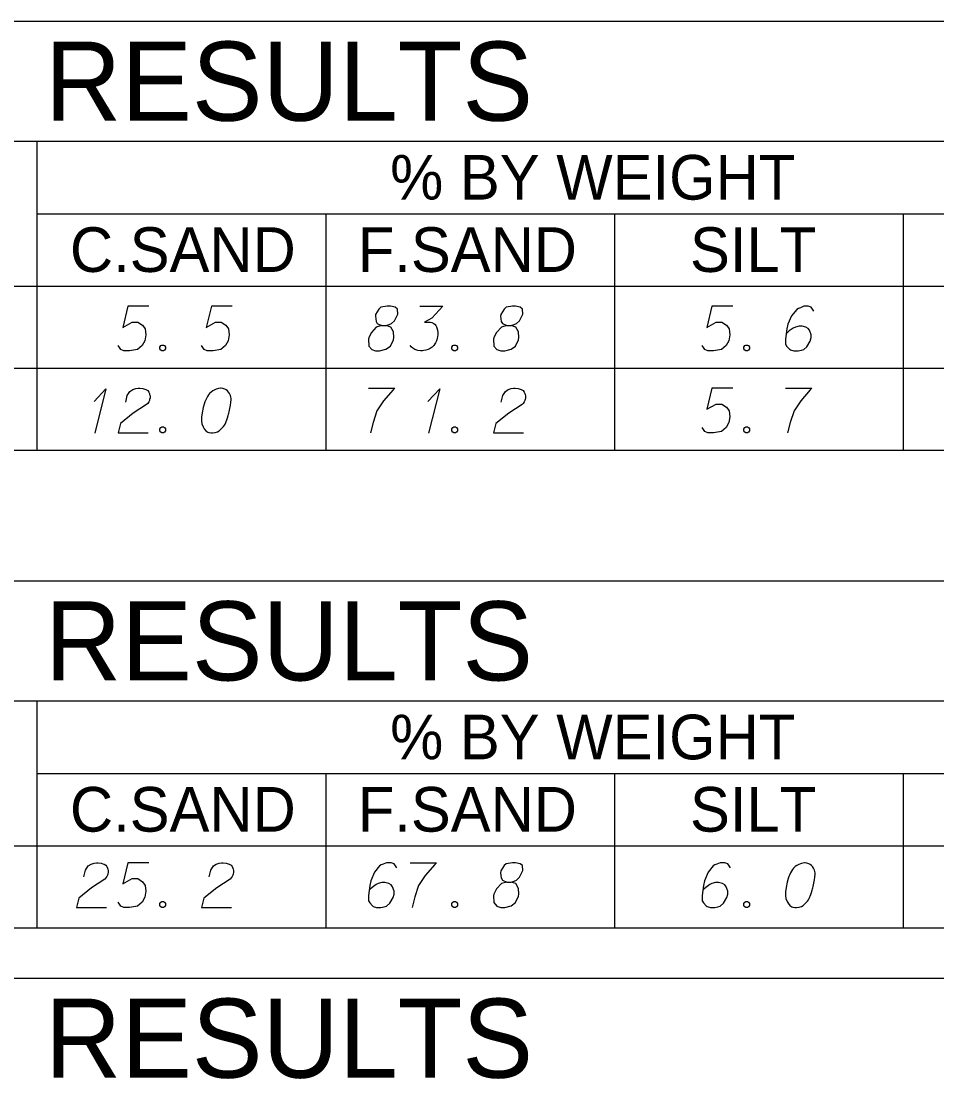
# Model space of a CAD drawing. Extents: x 2074207 to 2076812, y 516372 to 523312.
# Drawn here: x 2076524.4 to 2076622.7, y 516730.3 to 516843.9 of the extents above; entities that cross this region are included whole.
import ezdxf

# ---------------------------------------------------------------- set-up
doc = ezdxf.new("R2010")
doc.units = 0
for name, color, linetype in [('Prop DirtTable_ Soil Test Results - Outline (Major)', 7, 'Continuous'), ('Prop DirtTable_ Soil Test Results - Outline (Minor)', 7, 'Continuous'), ('Prop DirtTable_ Soil Test Results - Tx (Header - Large)', 7, 'Continuous'), ('Prop DirtTable_ Soil Test Results - Tx (Header - Small)', 7, 'Continuous'), ('Prop DirtTable_ Soil Test Results - Tx (Sample Data)', 7, 'Continuous')]:
    doc.layers.add(name, color=color, linetype=linetype)

msp = doc.modelspace()

# ---------------------------------------------------------------- linework, layer by layer
at = {"layer": 'Prop DirtTable_ Soil Test Results - Outline (Major)'}
for p, q in [((2076260.61, 516843.94), (2076811.9, 516843.94)), ((2076260.61, 516815.45), (2076811.9, 516815.45)), ((2076260.61, 516815.45), (2076811.9, 516815.45)), ((2076260.61, 516797.85), (2076811.9, 516797.85)), ((2076260.61, 516783.8), (2076811.9, 516783.8)), ((2076260.61, 516755.31), (2076811.9, 516755.31)), ((2076260.61, 516755.31), (2076811.9, 516755.31)), ((2076260.61, 516746.51), (2076811.9, 516746.51)), ((2076260.61, 516741.1), (2076811.9, 516741.1))]:
    msp.add_line(p, q, dxfattribs=at)
at = {"layer": 'Prop DirtTable_ Soil Test Results - Outline (Minor)'}
for p, q in [((2076260.61, 516831.05), (2076811.9, 516831.05)), ((2076526.07, 516831.05), (2076526.07, 516806.65)), ((2076526.07, 516823.25), (2076731.93, 516823.25)), ((2076557.09, 516823.25), (2076557.09, 516806.65)), ((2076588.11, 516823.25), (2076588.11, 516806.65)), ((2076619.13, 516806.65), (2076619.13, 516823.25)), ((2076260.61, 516806.65), (2076811.9, 516806.65)), ((2076260.61, 516806.65), (2076811.9, 516806.65)), ((2076526.07, 516806.65), (2076526.07, 516797.85)), ((2076557.09, 516806.65), (2076557.09, 516797.85)), ((2076588.11, 516806.65), (2076588.11, 516797.85)), ((2076619.13, 516797.85), (2076619.13, 516806.65)), ((2076260.61, 516797.85), (2076811.9, 516797.85)), ((2076260.61, 516770.91), (2076811.9, 516770.91)), ((2076526.07, 516770.91), (2076526.07, 516746.51)), ((2076526.07, 516763.11), (2076731.93, 516763.11)), ((2076557.09, 516763.11), (2076557.09, 516746.51)), ((2076588.11, 516763.11), (2076588.11, 516746.51)), ((2076619.13, 516746.51), (2076619.13, 516763.11)), ((2076260.61, 516746.51), (2076811.9, 516746.51))]:
    msp.add_line(p, q, dxfattribs=at)
at = {"layer": 'Prop DirtTable_ Soil Test Results - Tx (Sample Data)'}
for points in [[(2076538.08, 516813.3), (2076535.85, 516813.3), (2076535.29, 516811.03), (2076536.31, 516811.6), (2076536.91, 516811.6), (2076537.41, 516811.26), (2076537.69, 516810.88), (2076537.76, 516810.24), (2076537.65, 516809.6), (2076537.37, 516809.07), (2076536.88, 516808.65), (2076536.03, 516808.5), (2076535.4, 516808.5), (2076535.08, 516808.65), (2076534.8, 516809.07)], [(2076547.04, 516813.3), (2076544.81, 516813.3), (2076544.25, 516811.03), (2076545.27, 516811.6), (2076545.87, 516811.6), (2076546.37, 516811.26), (2076546.65, 516810.88), (2076546.72, 516810.24), (2076546.61, 516809.6), (2076546.33, 516809.07), (2076545.84, 516808.65), (2076544.99, 516808.5), (2076544.36, 516808.5), (2076544.04, 516808.65), (2076543.76, 516809.07)], [(2076563.09, 516811.22), (2076563.58, 516811.22), (2076563.72, 516811.26), (2076564.14, 516811.45), (2076564.46, 516811.75), (2076564.82, 516812.47), (2076564.78, 516813), (2076564.53, 516813.19), (2076564.04, 516813.3), (2076563.69, 516813.3), (2076563.02, 516813.19), (2076562.8, 516813), (2076562.45, 516812.43), (2076562.42, 516812.24), (2076562.49, 516811.67), (2076562.63, 516811.45), (2076563.09, 516811.22), (2076562.52, 516811.07), (2076561.99, 516810.5), (2076561.71, 516809.94), (2076561.68, 516809.75), (2076561.71, 516809.03), (2076562.03, 516808.65), (2076562.45, 516808.5), (2076562.87, 516808.5), (2076563.55, 516808.69), (2076564.04, 516809.03), (2076564.36, 516809.71), (2076564.39, 516809.94), (2076564.36, 516810.54), (2076564.07, 516811.07), (2076563.58, 516811.22)], [(2076567.18, 516813.3), (2076569.65, 516813.3), (2076568.48, 516812.01), (2076567.71, 516811.6), (2076568.34, 516811.6), (2076568.48, 516811.56), (2076568.55, 516811.52), (2076568.62, 516811.49), (2076568.7, 516811.45), (2076568.84, 516811.33), (2076568.91, 516811.22), (2076568.98, 516811.11), (2076569.01, 516810.99), (2076569.08, 516810.73), (2076569.12, 516810.5), (2076569.12, 516810.39), (2076569.12, 516810.24), (2076569.08, 516810.01), (2076569.05, 516809.86), (2076569.01, 516809.71), (2076568.98, 516809.6), (2076568.94, 516809.52), (2076568.91, 516809.44), (2076568.87, 516809.37), (2076568.8, 516809.26), (2076568.7, 516809.1), (2076568.59, 516808.99), (2076568.52, 516808.92), (2076568.41, 516808.84), (2076568.31, 516808.76), (2076568.17, 516808.69), (2076568.1, 516808.65), (2076567.85, 516808.58), (2076567.64, 516808.54), (2076567.5, 516808.5), (2076567.25, 516808.5), (2076566.97, 516808.54), (2076566.86, 516808.58), (2076566.76, 516808.61), (2076566.65, 516808.65), (2076566.54, 516808.73), (2076566.44, 516808.8), (2076566.26, 516808.95), (2076566.16, 516809.1)], [(2076576.53, 516811.22), (2076577.02, 516811.22), (2076577.16, 516811.26), (2076577.58, 516811.45), (2076577.9, 516811.75), (2076578.26, 516812.47), (2076578.22, 516813), (2076577.97, 516813.19), (2076577.48, 516813.3), (2076577.13, 516813.3), (2076576.46, 516813.19), (2076576.24, 516813), (2076575.89, 516812.43), (2076575.86, 516812.24), (2076575.93, 516811.67), (2076576.07, 516811.45), (2076576.53, 516811.22), (2076575.96, 516811.07), (2076575.43, 516810.5), (2076575.15, 516809.94), (2076575.12, 516809.75), (2076575.15, 516809.03), (2076575.47, 516808.65), (2076575.89, 516808.5), (2076576.31, 516808.5), (2076576.99, 516808.69), (2076577.48, 516809.03), (2076577.8, 516809.71), (2076577.83, 516809.94), (2076577.8, 516810.54), (2076577.51, 516811.07), (2076577.02, 516811.22)], [(2076600.8, 516813.3), (2076598.57, 516813.3), (2076598.01, 516811.03), (2076599.03, 516811.6), (2076599.63, 516811.6), (2076600.13, 516811.26), (2076600.41, 516810.88), (2076600.48, 516810.24), (2076600.37, 516809.6), (2076600.09, 516809.07), (2076599.6, 516808.65), (2076598.75, 516808.5), (2076598.12, 516808.5), (2076597.8, 516808.65), (2076597.52, 516809.07)], [(2076609.51, 516812.77), (2076609.23, 516813.19), (2076608.91, 516813.3), (2076608.42, 516813.3), (2076608.06, 516813.15), (2076607.85, 516813.07), (2076607.67, 516812.96), (2076607.11, 516812.28), (2076606.72, 516811.37), (2076606.62, 516810.88), (2076606.48, 516809.78), (2076606.48, 516809.22), (2076606.62, 516808.99), (2076606.9, 516808.69), (2076607, 516808.61), (2076607.36, 516808.5), (2076607.82, 516808.5), (2076608.17, 516808.58), (2076608.42, 516808.65), (2076608.77, 516808.95), (2076609.12, 516809.56), (2076609.23, 516809.94), (2076609.23, 516810.24), (2076609.05, 516810.73), (2076608.91, 516810.92), (2076608.66, 516811.07), (2076608.24, 516811.18), (2076607.92, 516811.18), (2076607.53, 516811.07), (2076607.29, 516810.96), (2076606.86, 516810.65), (2076606.65, 516810.46), (2076606.55, 516810.35)], [(2076539.49, 516809.14), (2076539.66, 516809.14), (2076539.77, 516809.07), (2076539.88, 516808.92), (2076539.88, 516808.73), (2076539.77, 516808.58), (2076539.66, 516808.5), (2076539.49, 516808.5), (2076539.38, 516808.58), (2076539.28, 516808.73), (2076539.28, 516808.92), (2076539.38, 516809.07), (2076539.49, 516809.14)], [(2076570.85, 516809.14), (2076571.02, 516809.14), (2076571.13, 516809.07), (2076571.24, 516808.92), (2076571.24, 516808.73), (2076571.13, 516808.58), (2076571.02, 516808.5), (2076570.85, 516808.5), (2076570.74, 516808.58), (2076570.64, 516808.73), (2076570.64, 516808.92), (2076570.74, 516809.07), (2076570.85, 516809.14)], [(2076602.21, 516809.14), (2076602.38, 516809.14), (2076602.49, 516809.07), (2076602.6, 516808.92), (2076602.6, 516808.73), (2076602.49, 516808.58), (2076602.38, 516808.5), (2076602.21, 516808.5), (2076602.1, 516808.58), (2076602, 516808.73), (2076602, 516808.92), (2076602.1, 516809.07), (2076602.21, 516809.14)], [(2076532.22, 516803.06), (2076533.49, 516804.42), (2076532.29, 516799.66)], [(2076535.61, 516802.99), (2076535.78, 516803.71), (2076536.07, 516804.16), (2076536.38, 516804.35), (2076536.7, 516804.46), (2076536.95, 516804.5), (2076537.12, 516804.5), (2076537.44, 516804.46), (2076537.65, 516804.39), (2076537.76, 516804.35), (2076537.97, 516804.24), (2076538.08, 516804.08), (2076538.15, 516803.93), (2076538.18, 516803.82), (2076538.22, 516803.67), (2076538.22, 516803.48), (2076538.18, 516803.29), (2076538.15, 516803.18), (2076538.08, 516803.03), (2076537.97, 516802.87), (2076537.86, 516802.76), (2076536.42, 516801.82), (2076535.04, 516800.72), (2076534.8, 516799.7), (2076538.01, 516799.7)], [(2076545.87, 516804.5), (2076545.8, 516804.5), (2076545.59, 516804.46), (2076545.45, 516804.42), (2076545.34, 516804.39), (2076545.17, 516804.31), (2076544.95, 516804.2), (2076544.78, 516804.08), (2076544.6, 516803.93), (2076544.5, 516803.78), (2076544.39, 516803.59), (2076544.28, 516803.4), (2076544.18, 516803.18), (2076544.11, 516803.03), (2076544.04, 516802.8), (2076543.93, 516802.42), (2076543.83, 516801.85), (2076543.76, 516801.4), (2076543.76, 516800.98), (2076543.79, 516800.68), (2076543.93, 516800.34), (2076544.04, 516800.15), (2076544.21, 516799.93), (2076544.43, 516799.78), (2076544.53, 516799.74), (2076544.74, 516799.7), (2076544.92, 516799.7), (2076545.2, 516799.74), (2076545.45, 516799.81), (2076545.63, 516799.93), (2076545.87, 516800.12), (2076545.98, 516800.23), (2076546.12, 516800.38), (2076546.22, 516800.53), (2076546.3, 516800.64), (2076546.37, 516800.83), (2076546.4, 516800.91), (2076546.47, 516801.1), (2076546.54, 516801.32), (2076546.61, 516801.55), (2076546.65, 516801.7), (2076546.68, 516801.82), (2076546.72, 516801.97), (2076546.79, 516802.31), (2076546.82, 516802.5), (2076546.86, 516802.69), (2076546.9, 516802.95), (2076546.93, 516803.29), (2076546.93, 516803.4), (2076546.9, 516803.55), (2076546.86, 516803.71), (2076546.75, 516803.93), (2076546.65, 516804.08), (2076546.54, 516804.2), (2076546.4, 516804.31), (2076546.26, 516804.39), (2076546.15, 516804.42), (2076546.05, 516804.46), (2076545.87, 516804.5)], [(2076561.68, 516804.5), (2076564.5, 516804.5), (2076564.32, 516804.31), (2076563.3, 516803.14), (2076562.59, 516802.08), (2076562.17, 516800.83), (2076561.89, 516799.7)], [(2076568.06, 516803.06), (2076569.33, 516804.42), (2076568.13, 516799.66)], [(2076575.93, 516802.99), (2076576.1, 516803.71), (2076576.39, 516804.16), (2076576.7, 516804.35), (2076577.02, 516804.46), (2076577.27, 516804.5), (2076577.44, 516804.5), (2076577.76, 516804.46), (2076577.97, 516804.39), (2076578.08, 516804.35), (2076578.29, 516804.24), (2076578.4, 516804.08), (2076578.47, 516803.93), (2076578.5, 516803.82), (2076578.54, 516803.67), (2076578.54, 516803.48), (2076578.5, 516803.29), (2076578.47, 516803.18), (2076578.4, 516803.03), (2076578.29, 516802.87), (2076578.18, 516802.76), (2076576.74, 516801.82), (2076575.36, 516800.72), (2076575.12, 516799.7), (2076578.33, 516799.7)], [(2076600.8, 516804.5), (2076598.57, 516804.5), (2076598.01, 516802.23), (2076599.03, 516802.8), (2076599.63, 516802.8), (2076600.13, 516802.46), (2076600.41, 516802.08), (2076600.48, 516801.44), (2076600.37, 516800.8), (2076600.09, 516800.27), (2076599.6, 516799.85), (2076598.75, 516799.7), (2076598.12, 516799.7), (2076597.8, 516799.85), (2076597.52, 516800.27)], [(2076606.48, 516804.5), (2076609.3, 516804.5), (2076609.12, 516804.31), (2076608.1, 516803.14), (2076607.39, 516802.08), (2076606.97, 516800.83), (2076606.69, 516799.7)], [(2076539.49, 516800.34), (2076539.66, 516800.34), (2076539.77, 516800.27), (2076539.88, 516800.12), (2076539.88, 516799.93), (2076539.77, 516799.78), (2076539.66, 516799.7), (2076539.49, 516799.7), (2076539.38, 516799.78), (2076539.28, 516799.93), (2076539.28, 516800.12), (2076539.38, 516800.27), (2076539.49, 516800.34)], [(2076570.85, 516800.34), (2076571.02, 516800.34), (2076571.13, 516800.27), (2076571.24, 516800.12), (2076571.24, 516799.93), (2076571.13, 516799.78), (2076571.02, 516799.7), (2076570.85, 516799.7), (2076570.74, 516799.78), (2076570.64, 516799.93), (2076570.64, 516800.12), (2076570.74, 516800.27), (2076570.85, 516800.34)], [(2076602.21, 516800.34), (2076602.38, 516800.34), (2076602.49, 516800.27), (2076602.6, 516800.12), (2076602.6, 516799.93), (2076602.49, 516799.78), (2076602.38, 516799.7), (2076602.21, 516799.7), (2076602.1, 516799.78), (2076602, 516799.93), (2076602, 516800.12), (2076602.1, 516800.27), (2076602.21, 516800.34)], [(2076531.13, 516751.99), (2076531.3, 516752.71), (2076531.59, 516753.16), (2076531.9, 516753.35), (2076532.22, 516753.46), (2076532.47, 516753.5), (2076532.64, 516753.5), (2076532.96, 516753.46), (2076533.17, 516753.39), (2076533.28, 516753.35), (2076533.49, 516753.24), (2076533.6, 516753.09), (2076533.67, 516752.93), (2076533.7, 516752.82), (2076533.74, 516752.67), (2076533.74, 516752.48), (2076533.7, 516752.29), (2076533.67, 516752.18), (2076533.6, 516752.03), (2076533.49, 516751.88), (2076533.38, 516751.76), (2076531.94, 516750.82), (2076530.56, 516749.72), (2076530.32, 516748.7), (2076533.53, 516748.7)], [(2076538.08, 516753.5), (2076535.85, 516753.5), (2076535.29, 516751.23), (2076536.31, 516751.8), (2076536.91, 516751.8), (2076537.41, 516751.46), (2076537.69, 516751.08), (2076537.76, 516750.44), (2076537.65, 516749.8), (2076537.37, 516749.27), (2076536.88, 516748.85), (2076536.03, 516748.7), (2076535.4, 516748.7), (2076535.08, 516748.85), (2076534.8, 516749.27)], [(2076544.57, 516751.99), (2076544.74, 516752.71), (2076545.03, 516753.16), (2076545.34, 516753.35), (2076545.66, 516753.46), (2076545.91, 516753.5), (2076546.08, 516753.5), (2076546.4, 516753.46), (2076546.61, 516753.39), (2076546.72, 516753.35), (2076546.93, 516753.24), (2076547.04, 516753.09), (2076547.11, 516752.93), (2076547.14, 516752.82), (2076547.18, 516752.67), (2076547.18, 516752.48), (2076547.14, 516752.29), (2076547.11, 516752.18), (2076547.04, 516752.03), (2076546.93, 516751.88), (2076546.82, 516751.76), (2076545.38, 516750.82), (2076544, 516749.72), (2076543.76, 516748.7), (2076546.97, 516748.7)], [(2076564.71, 516752.97), (2076564.43, 516753.39), (2076564.11, 516753.5), (2076563.62, 516753.5), (2076563.26, 516753.35), (2076563.05, 516753.27), (2076562.87, 516753.16), (2076562.31, 516752.48), (2076561.92, 516751.57), (2076561.82, 516751.08), (2076561.68, 516749.99), (2076561.68, 516749.42), (2076561.82, 516749.19), (2076562.1, 516748.89), (2076562.2, 516748.82), (2076562.56, 516748.7), (2076563.02, 516748.7), (2076563.37, 516748.78), (2076563.62, 516748.85), (2076563.97, 516749.16), (2076564.32, 516749.76), (2076564.43, 516750.14), (2076564.43, 516750.44), (2076564.25, 516750.93), (2076564.11, 516751.12), (2076563.86, 516751.27), (2076563.44, 516751.39), (2076563.12, 516751.39), (2076562.73, 516751.27), (2076562.49, 516751.16), (2076562.06, 516750.86), (2076561.85, 516750.67), (2076561.75, 516750.55)], [(2076566.16, 516753.5), (2076568.98, 516753.5), (2076568.8, 516753.31), (2076567.78, 516752.14), (2076567.07, 516751.08), (2076566.65, 516749.84), (2076566.37, 516748.7)], [(2076576.53, 516751.42), (2076577.02, 516751.42), (2076577.16, 516751.46), (2076577.58, 516751.65), (2076577.9, 516751.95), (2076578.26, 516752.67), (2076578.22, 516753.2), (2076577.97, 516753.39), (2076577.48, 516753.5), (2076577.13, 516753.5), (2076576.46, 516753.39), (2076576.24, 516753.2), (2076575.89, 516752.63), (2076575.86, 516752.44), (2076575.93, 516751.88), (2076576.07, 516751.65), (2076576.53, 516751.42), (2076575.96, 516751.27), (2076575.43, 516750.7), (2076575.15, 516750.14), (2076575.12, 516749.95), (2076575.15, 516749.23), (2076575.47, 516748.85), (2076575.89, 516748.7), (2076576.31, 516748.7), (2076576.99, 516748.89), (2076577.48, 516749.23), (2076577.8, 516749.91), (2076577.83, 516750.14), (2076577.8, 516750.74), (2076577.51, 516751.27), (2076577.02, 516751.42)], [(2076600.55, 516752.97), (2076600.27, 516753.39), (2076599.95, 516753.5), (2076599.46, 516753.5), (2076599.1, 516753.35), (2076598.89, 516753.27), (2076598.71, 516753.16), (2076598.15, 516752.48), (2076597.76, 516751.57), (2076597.66, 516751.08), (2076597.52, 516749.99), (2076597.52, 516749.42), (2076597.66, 516749.19), (2076597.94, 516748.89), (2076598.04, 516748.82), (2076598.4, 516748.7), (2076598.86, 516748.7), (2076599.21, 516748.78), (2076599.46, 516748.85), (2076599.81, 516749.16), (2076600.16, 516749.76), (2076600.27, 516750.14), (2076600.27, 516750.44), (2076600.09, 516750.93), (2076599.95, 516751.12), (2076599.7, 516751.27), (2076599.28, 516751.39), (2076598.96, 516751.39), (2076598.57, 516751.27), (2076598.33, 516751.16), (2076597.9, 516750.86), (2076597.69, 516750.67), (2076597.59, 516750.55)], [(2076608.59, 516753.5), (2076608.52, 516753.5), (2076608.31, 516753.46), (2076608.17, 516753.43), (2076608.06, 516753.39), (2076607.89, 516753.31), (2076607.67, 516753.2), (2076607.5, 516753.09), (2076607.32, 516752.93), (2076607.22, 516752.78), (2076607.11, 516752.59), (2076607, 516752.41), (2076606.9, 516752.18), (2076606.83, 516752.03), (2076606.76, 516751.8), (2076606.65, 516751.42), (2076606.55, 516750.86), (2076606.48, 516750.4), (2076606.48, 516749.99), (2076606.51, 516749.68), (2076606.65, 516749.34), (2076606.76, 516749.16), (2076606.93, 516748.93), (2076607.15, 516748.78), (2076607.25, 516748.74), (2076607.46, 516748.7), (2076607.64, 516748.7), (2076607.92, 516748.74), (2076608.17, 516748.82), (2076608.35, 516748.93), (2076608.59, 516749.12), (2076608.7, 516749.23), (2076608.84, 516749.38), (2076608.94, 516749.53), (2076609.02, 516749.65), (2076609.09, 516749.84), (2076609.12, 516749.91), (2076609.19, 516750.1), (2076609.26, 516750.33), (2076609.33, 516750.55), (2076609.37, 516750.7), (2076609.4, 516750.82), (2076609.44, 516750.97), (2076609.51, 516751.31), (2076609.54, 516751.5), (2076609.58, 516751.69), (2076609.62, 516751.95), (2076609.65, 516752.29), (2076609.65, 516752.41), (2076609.62, 516752.56), (2076609.58, 516752.71), (2076609.47, 516752.93), (2076609.37, 516753.09), (2076609.26, 516753.2), (2076609.12, 516753.31), (2076608.98, 516753.39), (2076608.87, 516753.43), (2076608.77, 516753.46), (2076608.59, 516753.5)], [(2076539.49, 516749.34), (2076539.66, 516749.34), (2076539.77, 516749.27), (2076539.88, 516749.12), (2076539.88, 516748.93), (2076539.77, 516748.78), (2076539.66, 516748.7), (2076539.49, 516748.7), (2076539.38, 516748.78), (2076539.28, 516748.93), (2076539.28, 516749.12), (2076539.38, 516749.27), (2076539.49, 516749.34)], [(2076570.85, 516749.34), (2076571.02, 516749.34), (2076571.13, 516749.27), (2076571.24, 516749.12), (2076571.24, 516748.93), (2076571.13, 516748.78), (2076571.02, 516748.7), (2076570.85, 516748.7), (2076570.74, 516748.78), (2076570.64, 516748.93), (2076570.64, 516749.12), (2076570.74, 516749.27), (2076570.85, 516749.34)], [(2076602.21, 516749.34), (2076602.38, 516749.34), (2076602.49, 516749.27), (2076602.6, 516749.12), (2076602.6, 516748.93), (2076602.49, 516748.78), (2076602.38, 516748.7), (2076602.21, 516748.7), (2076602.1, 516748.78), (2076602, 516748.93), (2076602, 516749.12), (2076602.1, 516749.27), (2076602.21, 516749.34)]]:
    msp.add_lwpolyline(points, dxfattribs=at)

# ---------------------------------------------------------------- texts
at = {"layer": 'Prop DirtTable_ Soil Test Results - Tx (Header - Large)'}
for p in [(2076465.66, 516833.24), (2076465.66, 516773.1), (2076465.66, 516730.41)]:
    msp.add_text('SOIL TEST RESULTS', height=8.5, dxfattribs=at).set_placement(p)
at = {"layer": 'Prop DirtTable_ Soil Test Results - Tx (Header - Small)'}
for s, p in [('% BY WEIGHT', (2076564.01, 516824.76)), ('C.SAND', (2076529.62, 516816.99)), ('F.SAND', (2076560.53, 516816.99)), ('SILT', (2076596.21, 516816.99)), ('% BY WEIGHT', (2076564.01, 516764.62)), ('C.SAND', (2076529.62, 516756.85)), ('F.SAND', (2076560.53, 516756.85)), ('SILT', (2076596.21, 516756.85))]:
    msp.add_text(s, height=4.8, dxfattribs=at).set_placement(p)

doc.saveas('drawing.dxf')
